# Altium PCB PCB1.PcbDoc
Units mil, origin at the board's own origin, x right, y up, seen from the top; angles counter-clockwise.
Board outline 3615 x 2110 mil, 2 copper layers (Top Layer, Bottom Layer); 10 components, 16 nets, 90 pads, 2 vias.
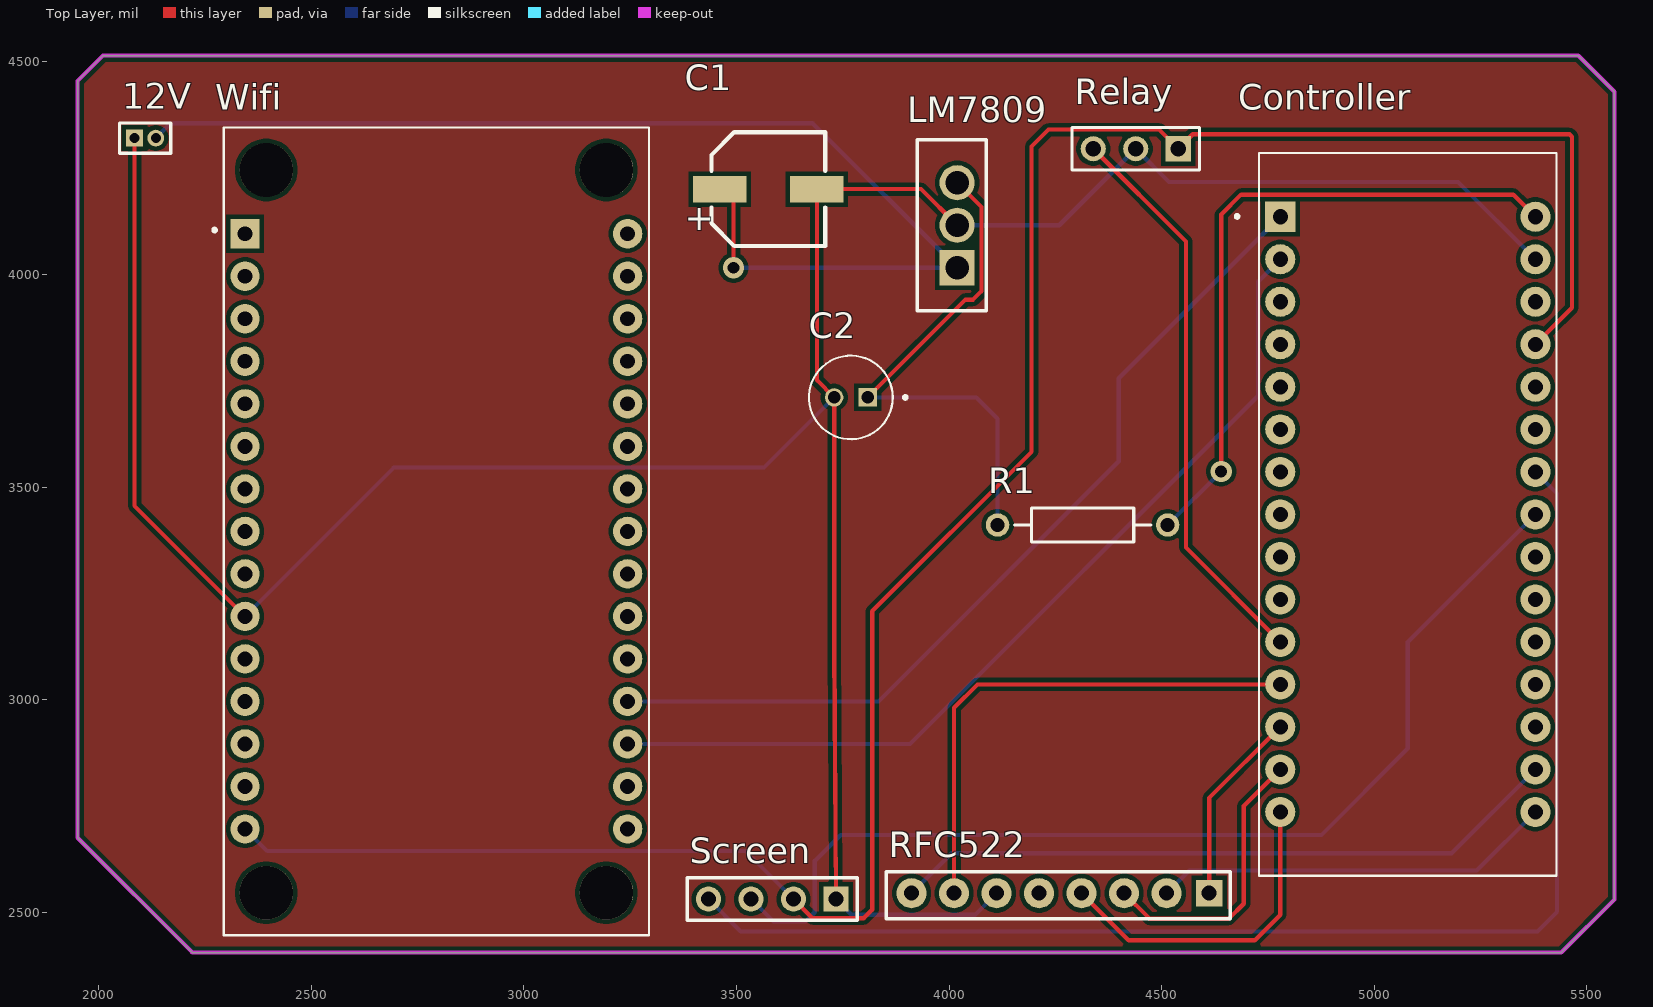
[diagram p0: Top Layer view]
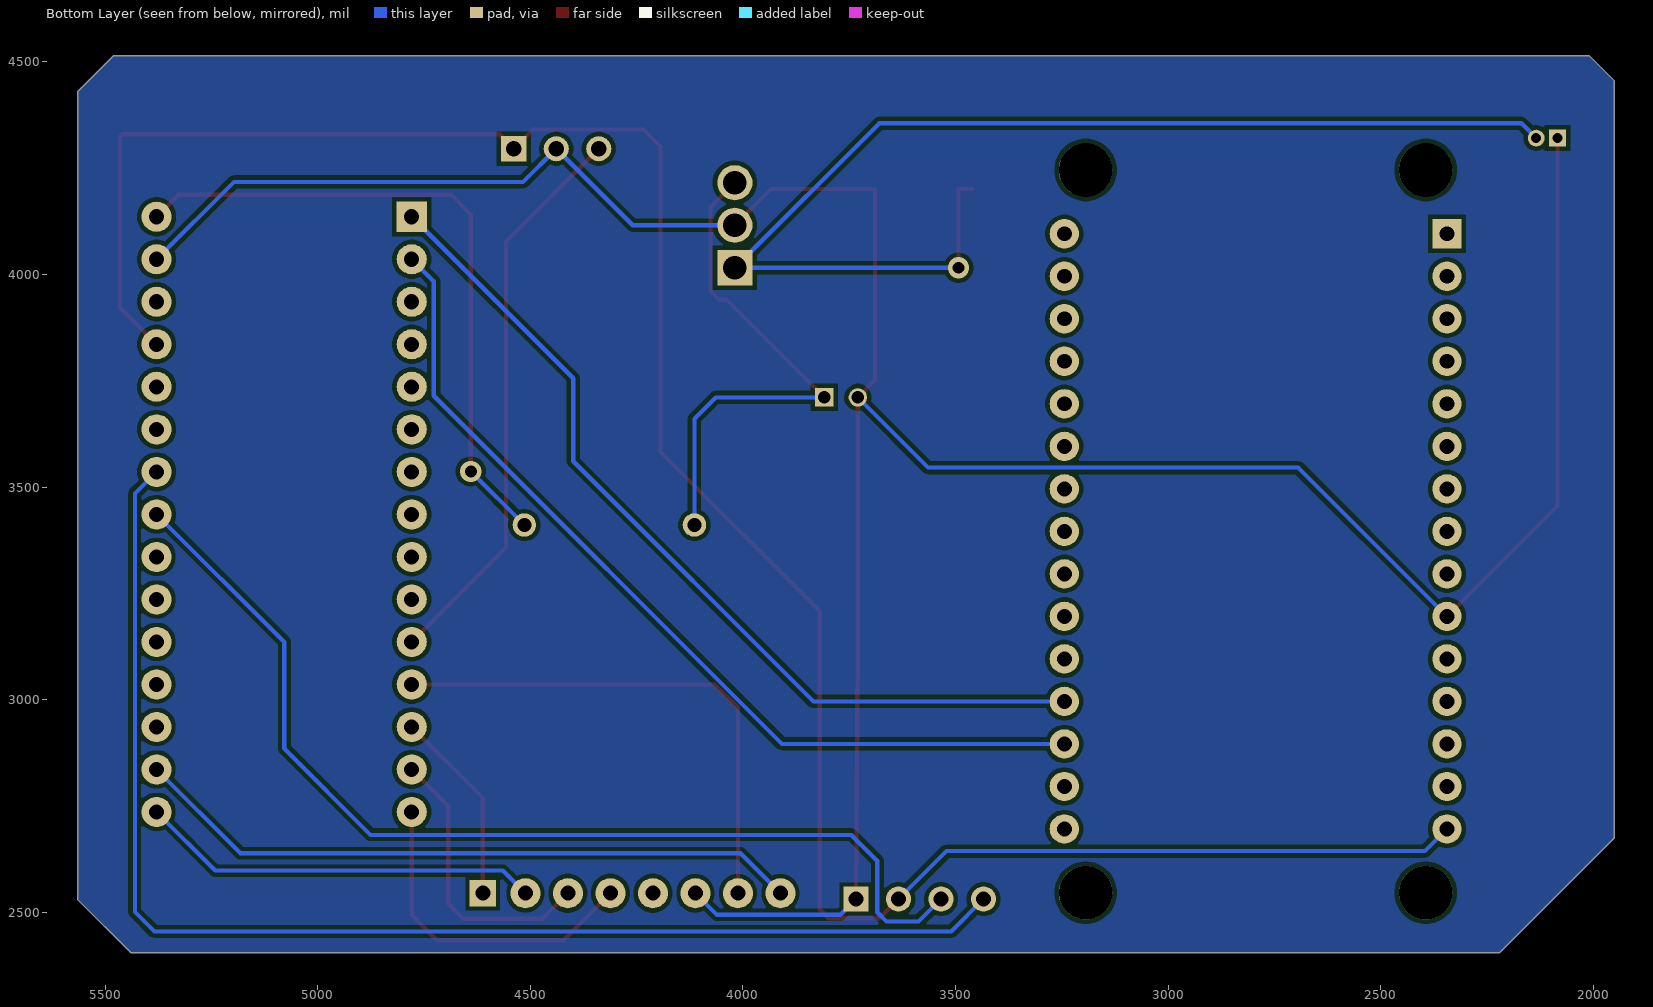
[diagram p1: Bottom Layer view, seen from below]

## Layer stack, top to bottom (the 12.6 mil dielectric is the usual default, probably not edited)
Top Solder: solder mask 0.4, Solder Resist, Dk 3.5
Top Layer: signal copper 1.4
Dielectric 1: dielectric 12.6, FR-4, Dk 4.8
Bottom Layer: signal copper 1.4
Bottom Solder: solder mask 0.4, Solder Resist, Dk 3.5

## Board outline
1950,2675 1950,4455 2010,4515 5480,4515 5565,4430 5565,2530 5440,2405 2220,2405

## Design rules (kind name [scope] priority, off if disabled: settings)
Clearance [All] p1: gap=10 ignorepadtopadclearanceinfootprint=FALSE except(0: Arc-Hole Track-Hole SMDPad-Hole THPad-Hole Via-Hole Fill-Hole Poly-Hole Region-Hole Text-Hole)
PolygonConnect [All] p1: connectstyle=Relief reliefconductorwidth=10 reliefentries=4 polygonreliefangle="90 Angle" airgapwidth=10
RoutingVias [All] p1: holewidth=28 width=50 viastyle="Through Hole" minholewidth=28 minwidth=50 maxholewidth=28 maxwidth=50
SolderMaskExpansion [All] p1: expansion=4 istentingtop=FALSE
Width [All] p1: maxlimit=10 minlimit=10 preferedwidth=10
30 further rules are at their usual default settings.

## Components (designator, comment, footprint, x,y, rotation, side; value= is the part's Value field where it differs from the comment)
12V "MHDR1X2" MHDR1X2 2084,4320.86 r0 top
C1 "100uF/16V" CAP_ALUM_SMD_6354_TYPE_D 3574.83,4200.86 r0 top
C2 "0.1uF" CAPPRD200W50D500H1100 3769,3710.86 r180 top
Controller "ARDUINO_NANO" SHIELD_ARDUINO_NANO 5079,3435.86 r0 top
LM7809 "LM7809CT" TO254P470X1016X1879-3P 4019,4015.86 r180 top
R1 "" AXIAL-0.4 4314,3410.86 r0 top value=1K
Relay "Header 3" HDR1X3 4539,4295.86 r180 top
RFC522 "" MFRC522_FURO 4264,2540.86 r180 top
Screen "Header 4" HDR1X4 3734,2530.86 r180 top
Wifi "ESP8266 NodeMCU" MODULE_ZC563900 2794,3395.86 r0 top

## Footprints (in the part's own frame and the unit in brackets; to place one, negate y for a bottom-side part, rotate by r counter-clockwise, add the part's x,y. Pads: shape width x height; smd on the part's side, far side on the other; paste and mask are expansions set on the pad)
AXIAL-0.4 [mm] "Axial Device, Thru-Hole; 2 Leads; 0.4 in Pin Spacing"
  round 1.4 hole 0.85: 1(-5.08,0) 2(5.08,0)
  silkscreen extent -4.06,-1.02 4.06,1.02
CAP_ALUM_SMD_6354_TYPE_D [mm] "Capacitor, Aluminum Electrolytic; 6.60 mm L X 6.60 mm W X 5.40 mm H body"
  rect 3.2x1.58 smd: 1(-2.9,0) 2(2.9,0)
  silkscreen extent -3.4,-3.4 3.4,3.4, body extent -3.47,-3.3 3.53,3.3, height 5.4
CAPPRD200W50D500H1100 [mm]
  round 1.1 hole 0.75: N(1,0)
  rect 1.1x1.1 hole 0.75: P(-1,0)
  silkscreen extent -3.35,-2.5 2.5,2.5, body extent -2.5,-2.5 2.5,2.5, height 11
HDR1X3 [mm] "Connector; Header; 3 Position"
  rect 1.5x1.5 hole 0.9: 1(0,0)
  round 1.5 hole 0.9: 2(2.54,0) 3(5.08,0)
  silkscreen extent -1.27,-1.27 6.35,1.27
HDR1X4 [mm] "Connector; Header; 4 Position"
  rect 1.5x1.5 hole 0.9: 1(0,0)
  round 1.5 hole 0.9: 2(2.54,0) 3(5.08,0) 4(7.62,0)
  silkscreen extent -1.27,-1.27 8.89,1.27
MFRC522_FURO [mm]
  rect 1.575x1.575 hole 0.889: 1(-8.832,-0.099)
  round 1.8 hole 0.889: 2(-6.292,-0.099) 3(-3.752,-0.099) 4(-1.212,-0.099) 5(1.328,-0.099) 6(3.868,-0.099) 7(6.408,-0.099) 8(8.948,-0.099)
  silkscreen extent -10.1,-1.37 10.47,1.42
MHDR1X2 [mm] "Connector; Header; 2 Position"
  rect 1x1 hole 0.6: 1(0,0)
  round 1 hole 0.6: 2(1.27,0)
  silkscreen extent -0.9,-0.9 2.17,0.9
MODULE_ZC563900 [mil]
  rect 69x69 / inner round 69 / far side rect 69x69 hole 35: 1(-450,700)
  round 69 hole 35: 2(-450,600) 3(-450,500) 4(-450,400) 5(-450,300) 6(-450,200) 7(-450,100) 8(-450,0) 9(-450,-100) 10(-450,-200) 11(-450,-300) 12(-450,-400) 13(-450,-500) 14(-450,-600) 15(-450,-700) 16(450,-700) 17(450,-600) 18(450,-500) 19(450,-400) 20(450,-300) 21(450,-200) 22(450,-100) 23(450,0) 24(450,100) 25(450,200) 26(450,300) 27(450,400) 28(450,500) 29(450,600) 30(450,700)
  round 125.98 hole 125.98 unplated: ""(-400,-850) ""(-400,850) ""(400,-850) ""(400,850)
  silkscreen extent -526,-950 500,950
SHIELD_ARDUINO_NANO [mm]
  rect 1.8x1.8 / inner round 1.8 / far side rect 1.8x1.8 hole 0.9: 1(-7.62,17.78)
  round 1.8 hole 0.9: 2(-7.62,15.24) 3(-7.62,12.7) 4(-7.62,10.16) 5(-7.62,7.62) 6(-7.62,5.08) 7(-7.62,2.54) 8(-7.62,0) 9(-7.62,-2.54) 10(-7.62,-5.08) 11(-7.62,-7.62) 12(-7.62,-10.16) 13(-7.62,-12.7) 14(-7.62,-15.24) 15(-7.62,-17.78) 16(7.62,-17.78) 17(7.62,-15.24) 18(7.62,-12.7) 19(7.62,-10.16) 20(7.62,-7.62) 21(7.62,-5.08) 22(7.62,-2.54) 23(7.62,0) 24(7.62,2.54) 25(7.62,5.08) 26(7.62,7.62) 27(7.62,10.16) 28(7.62,12.7) 29(7.62,15.24) 30(7.62,17.78)
  silkscreen extent -10.3,-21.59 8.89,21.59, body extent -9,-21.6 9,23.4, height 12.6
TO254P470X1016X1879-3P [mm]
  rect 2.1x2.1 hole 1.4: 1(0,0)
  round 2.1 hole 1.4: 2(0,-2.54) 3(0,-5.08)
  silkscreen extent -1.74,-7.64 2.4,2.56

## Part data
12V: "Header, 2-Pin"
C1: library part EEE-FK1C101P, "CAP ALUM 100uF 20% 16V SMD", MFR=Panasonic
C2: library part EEUEB1J1R0S, "CAP ALUM 1UF 20% 63V RADIAL", Package="RADIAL-2 Panasonic"
Controller: "Small, complete, and breadboard-friendly board based on the ATmega328 (Arduino Nano 3.x)", Package="Non-Standard Arduino"
LM7809: "Linear Voltage Regulator IC 1 Output 1A TO-220-3", Package="TO-220-3 Fujitsu"
R1: library part Res2, "Resistor"
Relay: "Header, 3-Pin"
RFC522: library part MFRC522_SYM
Screen: "Header, 4-Pin"
Wifi: library part ZC563900, "NodeMcu Lua ESP8266 WIFI Internet of Things Network Development Module Board", Package=None

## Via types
v1: diameter 50, hole 28, Top Layer to Bottom Layer, 2 vias

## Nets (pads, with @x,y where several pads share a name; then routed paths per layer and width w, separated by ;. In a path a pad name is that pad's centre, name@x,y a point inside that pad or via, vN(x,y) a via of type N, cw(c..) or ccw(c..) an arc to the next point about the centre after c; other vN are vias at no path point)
Net12V_1: 12V.1 C1.2 C2.N Controller.29 LM7809.2 Relay.2 RFC522.6 Screen.1 Wifi.10 | length 6840.1
  Top Layer w10: 12V.1 2084,3455.86 Wifi.10 ; Screen.1 3729.63,3125.23 C2.N 3689,3751.49 C1.2 3934,4200.86 LM7809.2
  Bottom Layer w10: Wifi.10 2694,3545.86 3564.63,3545.86 C2.N ; Screen.1 3771,2493.86 4060.82,2493.86 RFC522.6 ; LM7809.2 4259,4115.86 Relay.2 4517,4217.86 5197,4217.86 Controller.29
Net12V_2: 12V.2 C1.1 LM7809.1 | length 2783.7
  Top Layer w10: C1.1 3493,4200.86 v1(3493,4015.86)
  Bottom Layer w10: 12V.2 2169,4355.86 3679,4355.86 LM7809.1 v1(3493,4015.86)
NetC2_P: C2.P LM7809.3 R1.1 | length 1226.1
  Top Layer w10: C2.P 4038.37,3940.86 4056,3940.86 4076,3960.86 4076,4158.86 LM7809.3
  Bottom Layer w10: C2.P 4064,3710.86 4114,3660.86 R1.1
NetController_1: Controller.1 Wifi.19 | length 2121.4
  Bottom Layer w10: Wifi.19 3834,2995.86 4399,3560.86 4399,3755.86 Controller.1
NetController_2: Controller.2 Wifi.18 | length 2164.8
  Bottom Layer w10: Wifi.18 3908,2895.86 4727,3714.86 4727,3983.86 Controller.2
NetController_11: Controller.11 Relay.3 | length 1342.3
  Top Layer w10: Relay.3 4557,4077.86 4557,3357.86 Controller.11
NetController_12: Controller.12 RFC522.7 | length 1226.2
  Top Layer w10: RFC522.7 4011.72,2980.86 4066.72,3035.86 Controller.12
NetController_13: Controller.13 RFC522.1 | length 460.4
  Top Layer w10: RFC522.1 4611.72,2768.57 Controller.13
NetController_14: Controller.14 RFC522.3 | length 672.2
  Top Layer w10: RFC522.3 4471.62,2484.86 4658,2484.86 4693,2519.86 4693,2749.86 Controller.14
NetController_15: Controller.15 RFC522.4 | length 780.1
  Top Layer w10: RFC522.4 4422.62,2433.86 4719,2433.86 4779,2493.86 Controller.15
NetController_16: Controller.16 RFC522.2 | length 946.4
  Bottom Layer w10: RFC522.2 4564.82,2597.86 5241,2597.86 Controller.16
NetController_17: Controller.17 RFC522.8 | length 1587.9
  Bottom Layer w10: RFC522.8 4005.82,2638.86 5182,2638.86 Controller.17
NetController_23: Controller.23 Screen.3 | length 2481.4
  Bottom Layer w10: Screen.3 3586.68,2478.17 3662.32,2478.17 3684,2499.86 3684,2620.86 3745,2681.86 4876,2681.86 5079,2884.86 5079,3135.86 Controller.23
NetController_24: Controller.24 Screen.4 | length 3102.7
  Bottom Layer w10: Screen.4 3510,2454.86 5384,2454.86 5430,2500.86 5430,3484.86 Controller.24
NetController_27: Controller.27 Relay.1 Screen.2 Wifi.15 | length 5367.3
  Top Layer w10: Screen.2 3679,2485.86 3799,2485.86 3819,2505.86 3819,3207.86 4194,3582.86 4194,4300.86 4234,4340.86 4494,4340.86 Relay.1 4573.14,4330 5459.14,4330 5465,4324.14 5465,3921.86 Controller.27
  Bottom Layer w10: Wifi.15 2396,2643.86 3521,2643.86 Screen.2
NetController_30: Controller.30 R1.2 | length 1562.2
  Top Layer w10: v1(4640,3536.86) 4640,4140.86 4687,4187.86 5327,4187.86 Controller.30
  Bottom Layer w10: R1.2 v1(4640,3536.86)
pads on no net: Controller.3 Controller.4 Controller.5 Controller.6 Controller.7 Controller.8 Controller.9 Controller.10 Controller.18 Controller.19 Controller.20 Controller.21 Controller.22 Controller.25 Controller.26 Controller.28 RFC522.5 Wifi. Wifi.1 Wifi.2 Wifi.3 Wifi.4 Wifi.5 Wifi.6 Wifi.7 Wifi.8 Wifi.9 Wifi.11 Wifi.12 Wifi.13 Wifi.14 Wifi.16 Wifi.17 Wifi.20 Wifi.21 Wifi.22 Wifi.23 Wifi.24 Wifi.25 Wifi.26 Wifi.27 Wifi.28 Wifi.29 Wifi.30

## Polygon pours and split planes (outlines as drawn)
no net on Top Layer "NONET_L01_P000" (solid, pour order 0): 2010,4515 5480,4515 5565,4430 5565,2530 5440,2405 2220,2405 1950,2675 1950,4455
no net on Bottom Layer "NONET_L02_P002" (solid, pour order 2): 2010,4515 5480,4515 5565,4430 5565,2530 5440,2405 2220,2405 1950,2675 1950,4455

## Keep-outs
Top Layer:
  the board outline again, w10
